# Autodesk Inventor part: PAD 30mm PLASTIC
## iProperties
Created: 2007-03
Part Number: PAD 30mm PLASTIC
Document SubType Name: Modeling
Designer: Andy Moles
Material: ABS Plastic
Density: 1.06 g/cm^3
Mass: 7.67338 g
Surface Area: 34.4947 cm^2
Volume: 7.23904 cm^3
Author: Andy Moles
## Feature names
1. Revolution1
2. Extrusion1
3. Extrusion2
